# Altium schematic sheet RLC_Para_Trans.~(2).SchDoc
size A4
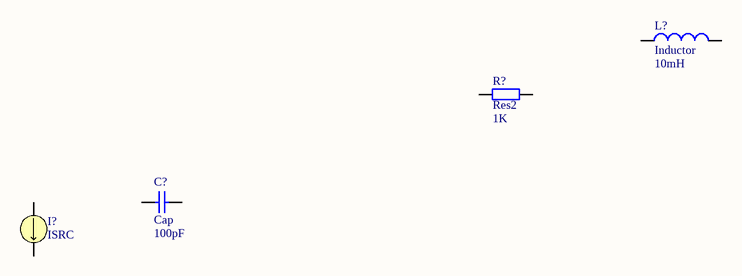
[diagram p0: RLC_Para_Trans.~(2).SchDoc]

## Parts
C?  Cap  value 100pF  [RAD-0.3]
I?  ISRC
L?  Inductor  value 10mH  [0402-A]
R?  Res2  value 1K  [AXIAL-0.4]

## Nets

Not connected (* = marked no-connect by the designer): C? 1 2; I? 1 2; L? 1 2; R? 1 2

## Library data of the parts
C? = Cap: Capacitor
I? = ISRC: Current Source; Note: PCB Footprint - Not required
L? = Inductor: Code_IEC: 1005
R? = Res2: Resistor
